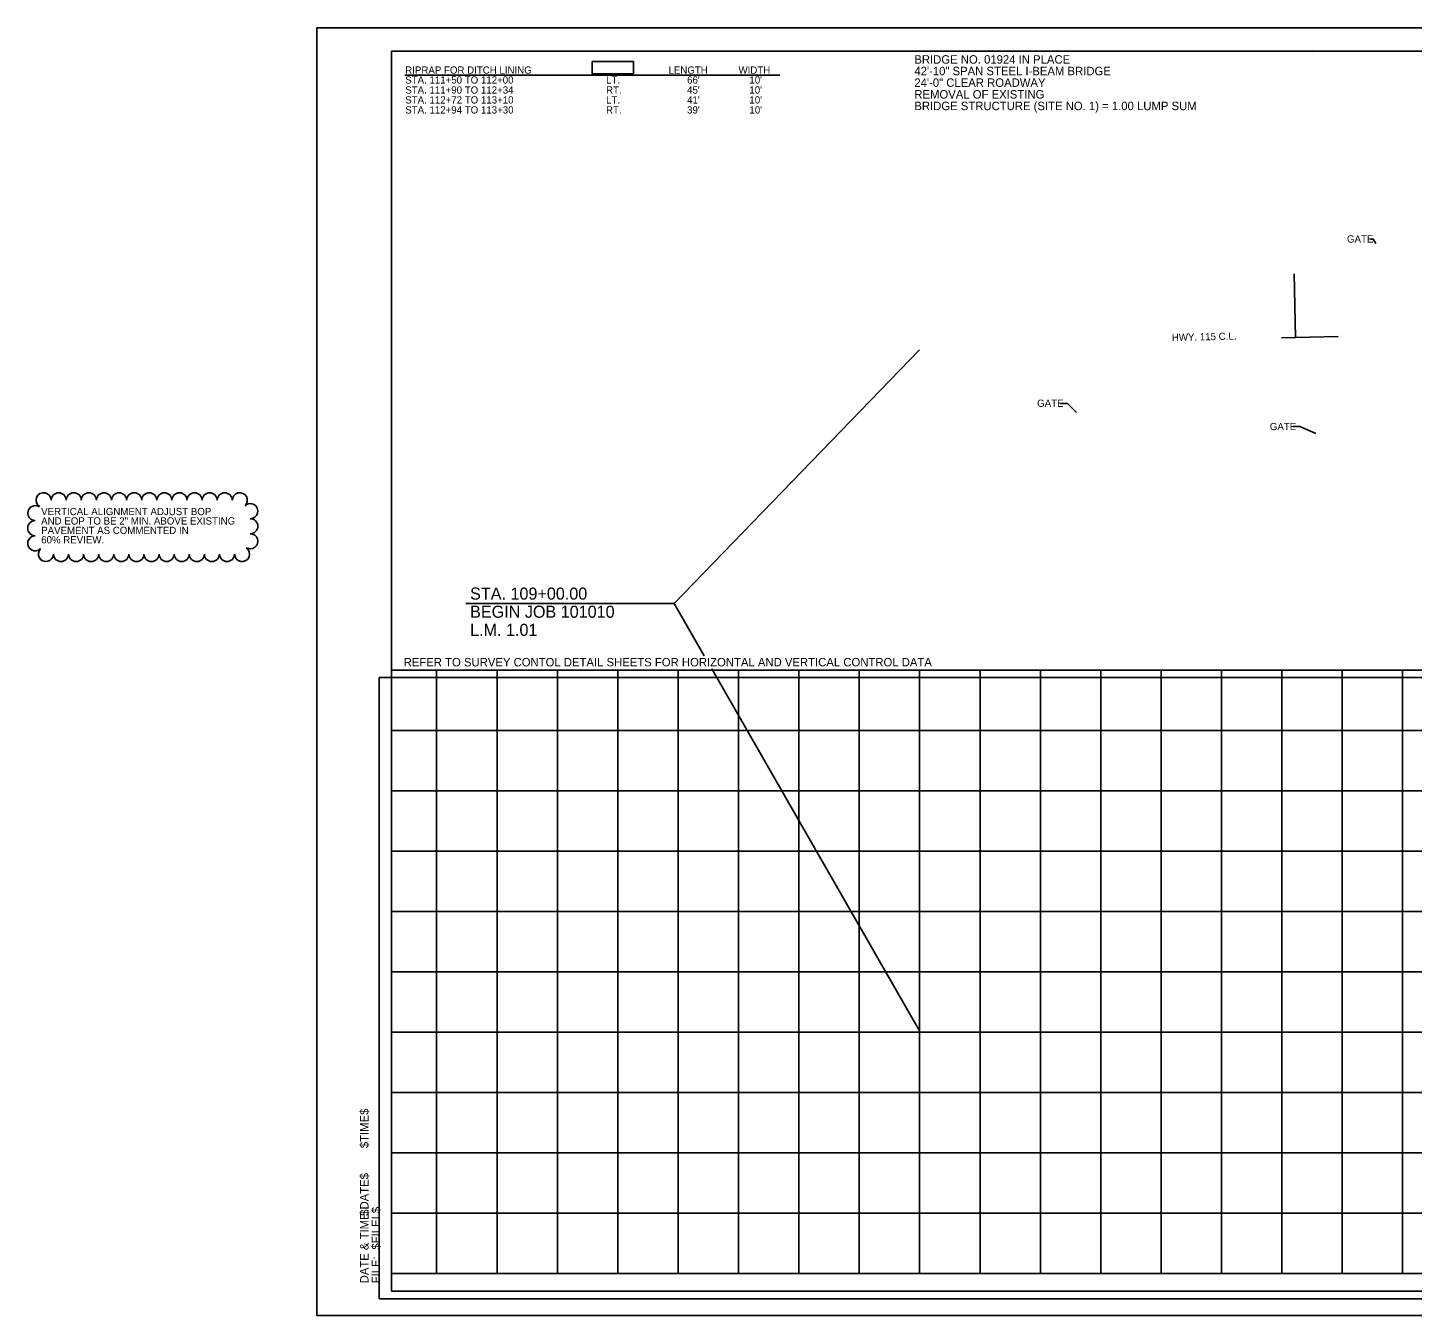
# Model space of a CAD drawing. Extents: x 9709 to 12772, y 9986 to 11806.
# Drawn here: x 9709 to 10855, y 9986 to 11053 of the extents above; entities that cross this region are included whole.
import ezdxf

# ---------------------------------------------------------------- set-up
doc = ezdxf.new("R2010")
doc.units = 0
for name, color, linetype in [('_30% NOTES', 7, 'Continuous'), ('Dumped RipRap Annot', 7, 'Continuous'), ('GREEN_TXT', 7, 'Continuous'), ('JOB Text', 7, 'Continuous'), ('NOTES', 7, 'Continuous'), ('R_No Plot', 7, 'Continuous'), ('R_Proposed Const Limits Annot', 7, 'Continuous'), ('SEAL-INFO', 7, 'Continuous'), ('TEXT', 7, 'Continuous')]:
    doc.layers.add(name, color=color, linetype=linetype)

msp = doc.modelspace()

# ---------------------------------------------------------------- linework, layer by layer
at = {"layer": '_30% NOTES'}
for centre, start, end in [((9722, 10661.6), 0, 236.9636), ((9734.5, 10661.6), 0, 180), ((9747, 10661.6), 0, 180), ((9759.5, 10661.6), 0, 180), ((9772, 10661.6), 0, 180), ((9784.5, 10661.6), 0, 180), ((9797, 10661.6), 0, 180), ((9809.5, 10661.6), 0, 180), ((9822, 10661.6), 0, 180), ((9834.5, 10661.6), 0, 180), ((9847, 10661.6), 0, 180), ((9859.5, 10661.6), 0, 180), ((9872, 10661.6), 0, 180), ((9884.5, 10661.6), 314.1183, 180), ((9715.1, 10651), 56.9636, 270), ((9893.2, 10652.6), 270, 134.1183), ((9715.1, 10638.5), 90, 270), ((9893.2, 10640.1), 270, 90), ((9715.1, 10626), 90, 314.8317), ((9893.2, 10627.6), 237.0496, 90), ((9723.9, 10617.1), 134.8317, 0), ((9886.4, 10617.1), 180, 57.0496), ((9736.4, 10617.1), 180, 0), ((9748.9, 10617.1), 180, 0), ((9761.4, 10617.1), 180, 0), ((9773.9, 10617.1), 180, 0), ((9786.4, 10617.1), 180, 0), ((9798.9, 10617.1), 180, 0), ((9811.4, 10617.1), 180, 0), ((9823.9, 10617.1), 180, 0), ((9836.4, 10617.1), 180, 0), ((9848.9, 10617.1), 180, 0), ((9861.4, 10617.1), 180, 0), ((9873.9, 10617.1), 180, 0)]:
    msp.add_arc(centre, 6.25, start, end, dxfattribs=at)
at = {"layer": 'Dumped RipRap Annot'}
msp.add_line((10021.2, 11013.8), (10331.7, 11013.8), dxfattribs=at)
msp.add_lwpolyline([(10176.4, 11025.1), (10210.4, 11025.1), (10210.4, 11015), (10176.4, 11015)], close=True, dxfattribs=at)
at = {"layer": 'GREEN_TXT'}
for p, q in [((10010.2, 11033.6), (11591.1, 11033.6)), ((10010.2, 10006.3), (10010.2, 11033.6)), ((10772.8, 11032.3), (10772.8, 11032.3)), ((10772.8, 11032.3), (10772.8, 11032.3)), ((11591.1, 10521), (10010.2, 10521)), ((10047.5, 10021), (10047.5, 10521)), ((10097.5, 10021), (10097.5, 10521)), ((10147.5, 10021), (10147.5, 10521)), ((10197.5, 10021), (10197.5, 10521)), ((10247.5, 10021), (10247.5, 10521)), ((10297.5, 10021), (10297.5, 10521)), ((10347.5, 10021), (10347.5, 10521)), ((10397.5, 10021), (10397.5, 10521)), ((10447.5, 10021), (10447.5, 10521)), ((10497.5, 10021), (10497.5, 10521)), ((10547.5, 10021), (10547.5, 10521)), ((10597.5, 10021), (10597.5, 10521)), ((10647.5, 10021), (10647.5, 10521)), ((10697.5, 10021), (10697.5, 10521)), ((10747.5, 10021), (10747.5, 10521)), ((10797.5, 10021), (10797.5, 10521)), ((10847.5, 10021), (10847.5, 10521)), ((11591.1, 10471), (10010.2, 10471)), ((11591.1, 10421), (10010.2, 10421)), ((11591.1, 10371), (10010.2, 10371)), ((11591.1, 10321), (10010.2, 10321)), ((11591.1, 10271), (10010.2, 10271)), ((11591.1, 10221), (10010.2, 10221)), ((11591.1, 10171), (10010.2, 10171)), ((11591.1, 10121), (10010.2, 10121)), ((11591.1, 10071), (10010.2, 10071)), ((11591.1, 10021), (10010.2, 10021)), ((10010.2, 10006.3), (10010.2, 10006.3)), ((11591.1, 10006.3), (10010.2, 10006.3))]:
    msp.add_line(p, q, dxfattribs=at)
at = {"layer": 'JOB Text'}
for p, q in [((10244.2, 10576.1), (10269.1, 10532.7)), ((10275.4, 10521.9), (10447.5, 10222.1))]:
    msp.add_line(p, q, dxfattribs=at)
msp.add_lwpolyline([(10071.6, 10576.1), (10244.2, 10576.1), (10447.4, 10786.3)], dxfattribs=at)
at = {"layer": 'R_No Plot'}
for p, q in [((9948.2, 11053.1), (11614.8, 11053.1)), ((9948.2, 9986.4), (11614.8, 9986.4))]:
    msp.add_line(p, q, dxfattribs=at)
for points in [[(9948.2, 11053.1), (11614.9, 11053.1), (11614.9, 9986.4), (9948.2, 9986.4)], [(11179.8, 11033.6), (11179.8, 10984.2), (11358.4, 10984.2), (11358.4, 10969.6), (11477.6, 10969.6), (11477.6, 10851.2), (11591.1, 10851.2), (11591.1, 10521), (10010.2, 10521), (10010.2, 11033.6)]]:
    msp.add_lwpolyline(points, close=True, dxfattribs=at)
at = {"layer": 'R_Proposed Const Limits Annot'}
msp.add_line((10647.5, 10021), (10727.5, 10021), dxfattribs=at)
at = {"layer": 'SEAL-INFO'}
for points in [[(11326.3, 10984.2), (11179.8, 10984.2), (11179.8, 11033.6), (10010.2, 11033.6), (10010.2, 10521), (11297.5, 10521), (11591.1, 10521), (11591.1, 10556), (11591.1, 10556), (11591.1, 10969.6), (11326.3, 10969.6)], [(10000, 10000), (11574.6, 10000), (11574.6, 10514.7), (10000, 10514.7)]]:
    msp.add_lwpolyline(points, close=True, dxfattribs=at)
at = {"layer": 'TEXT'}
for p, q in [((10757.6, 10849.3), (10758.8, 10796.4)), ((10747.2, 10796.2), (10794, 10797.3))]:
    msp.add_line(p, q, dxfattribs=at)
for points in [[(10820.8, 10878), (10823.2, 10878), (10825.3, 10874.3)], [(10564.1, 10741.8), (10569.8, 10741.8), (10577.3, 10734.3)], [(10756.8, 10722.8), (10762.4, 10722.8), (10775.7, 10716.8)]]:
    msp.add_lwpolyline(points, dxfattribs=at)

# ---------------------------------------------------------------- texts
for s, p in [('$TIME$', (9991.1, 10124.9)), ('$DATE$', (9991.1, 10068.9)), ('DATE & TIME:', (9991.1, 10012.9)), ('$FILEL$', (10000.7, 10040.9)), ('FILE: ', (10000.7, 10012.9))]:
    msp.add_text(s, height=7, rotation=90).set_placement(p)
at = {"layer": '_30% NOTES'}
for s, p in [('VERTICAL ALIGNMENT ADJUST BOP', (9720, 10649.3)), ('AND EOP TO BE 2" MIN. ABOVE EXISTING', (9720, 10641.5)), ('60% REVIEW.', (9720, 10625.9)), ('PAVEMENT AS COMMENTED IN ', (9720, 10633.7))]:
    msp.add_text(s, height=6, dxfattribs=at).set_placement(p)
at = {"layer": 'Dumped RipRap Annot'}
for s, p in [('RIPRAP FOR DITCH LINING', (10021.5, 11015)), ('LENGTH', (10239.5, 11015)), ('WIDTH', (10297.5, 11015)), ('STA. 111+50 TO 112+00', (10021.5, 11006.8)), ('LT.', (10187.8, 11006.8)), ("66'", (10254.9, 11006.8)), ("10'", (10306.5, 11006.8)), ('STA. 111+90 TO 112+34', (10021.5, 10998.5)), ('RT.', (10187.8, 10998.5)), ("45'", (10254.9, 10998.5)), ("10'", (10306.5, 10998.5)), ('STA. 112+72 TO 113+10', (10021.5, 10990.3)), ('STA. 112+94 TO 113+30', (10021.5, 10982)), ('LT.', (10187.8, 10990.3)), ('RT.', (10187.8, 10982)), ("41'", (10254.9, 10990.3)), ("39'", (10254.9, 10982)), ("10'", (10306.5, 10990.3)), ("10'", (10306.5, 10982))]:
    msp.add_text(s, height=6, dxfattribs=at).set_placement(p)
at = {"layer": 'JOB Text'}
for s, p in [('STA. 109+00.00', (10075.2, 10579.3)), ('BEGIN JOB 101010', (10075.2, 10564.3)), ('L.M. 1.01', (10075.2, 10549.3))]:
    msp.add_text(s, height=10, dxfattribs=at).set_placement(p)
at = {"layer": 'NOTES'}
for s, p in [('42\'-10" SPAN STEEL I-BEAM BRIDGE', (10443.1, 11013.7)), ('BRIDGE NO. 01924 IN PLACE', (10443.1, 11023.3)), ('24\'-0" CLEAR ROADWAY', (10443.1, 11004.1)), ('REMOVAL OF EXISTING ', (10443.1, 10994.4)), ('BRIDGE STRUCTURE (SITE NO. 1) = 1.00 LUMP SUM', (10443.1, 10984.8))]:
    msp.add_text(s, height=7, dxfattribs=at).set_placement(p)
at = {"layer": 'TEXT'}
for s, height, p in [('GATE', 6, (10801.4, 10875.1)), ('GATE', 6, (10544.8, 10739)), ('GATE', 6, (10737.5, 10719.7)), ('REFER TO SURVEY CONTOL DETAIL SHEETS FOR HORIZONTAL AND VERTICAL CONTROL DATA', 7, (10020.2, 10524))]:
    msp.add_text(s, height=height, dxfattribs=at).set_placement(p)
msp.add_text('HWY. 115 C.L.', height=6, rotation=1.3113, dxfattribs=at).set_placement((10656.4, 10793.5))

doc.saveas('drawing.dxf')
